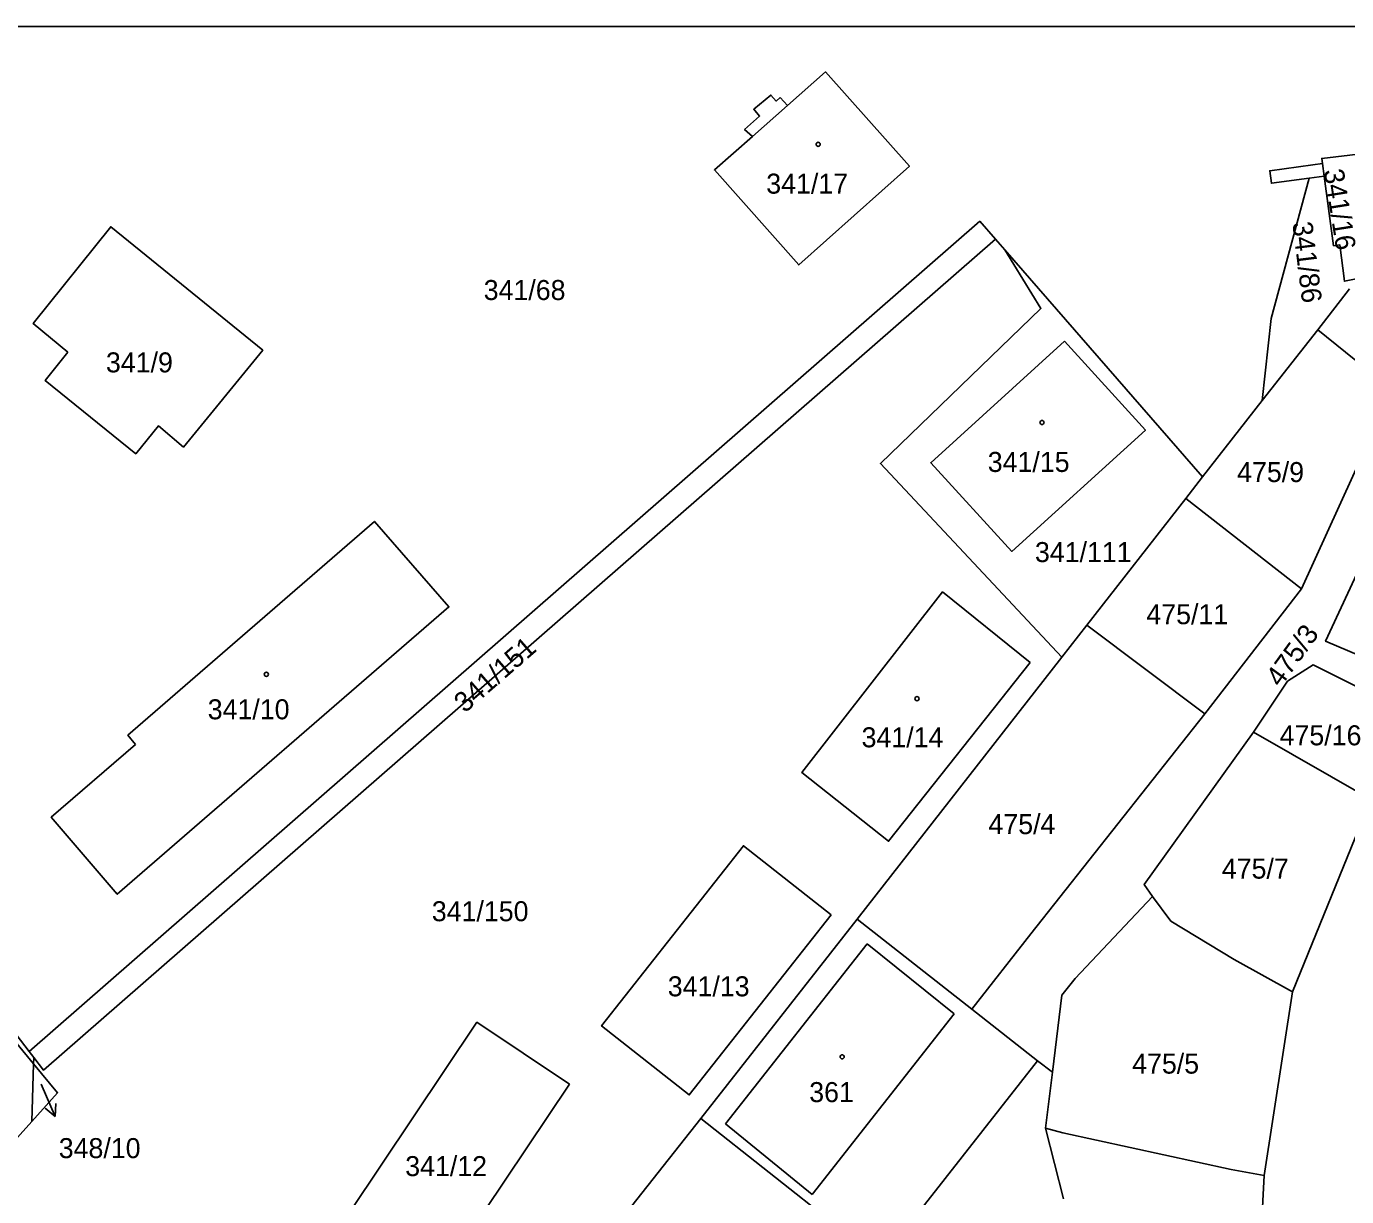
# Model space of a CAD drawing. Extents: x -558358 to -557517, y -1073785 to -1073189.
# Drawn here: x -557909.7 to -557797.5, y -1073289.5 to -1073190.1 of the extents above; entities that cross this region are included whole.
import ezdxf

# ---------------------------------------------------------------- set-up
doc = ezdxf.new("R2010")
doc.units = 0
for name, color, linetype in [('Hranice parcel', 7, 'Continuous'), ('Parcelní čísla', 7, 'Continuous'), ('Pop  PČ popisy', 7, 'Continuous'), ('Rozpiska_pole_1', 7, 'Continuous'), ('Vnitřní kresba', 7, 'Continuous'), ('Značky budov', 7, 'Continuous')]:
    doc.layers.add(name, color=color, linetype=linetype)

msp = doc.modelspace()

# ---------------------------------------------------------------- linework, layer by layer
at = {"layer": 'Hranice parcel'}
for p, q in [((-557909.46, -1073277.19), (-557828.67, -1073206.65)), ((-557828.67, -1073206.65), (-557827.35, -1073208.16)), ((-557827.35, -1073208.16), (-557826.56, -1073209.07)), ((-557826.56, -1073209.07), (-557809.74, -1073228.36)), ((-557797.26, -1073212.4), (-557799.96, -1073215.86)), ((-557799.96, -1073215.86), (-557804.68, -1073221.89)), ((-557809.74, -1073228.36), (-557804.68, -1073221.89)), ((-557809.74, -1073228.36), (-557811.18, -1073230.2)), ((-557811.18, -1073230.2), (-557819.59, -1073240.96)), ((-557811.18, -1073230.2), (-557801.34, -1073237.87)), ((-557801.34, -1073237.87), (-557809.56, -1073248.5)), ((-557819.59, -1073240.96), (-557821.71, -1073243.68)), ((-557809.56, -1073248.5), (-557819.59, -1073240.96)), ((-557821.71, -1073243.68), (-557839.11, -1073265.95)), ((-557795.47, -1073255.77), (-557805.42, -1073250.06)), ((-557909.08, -1073278.25), (-557930.32, -1073252.64)), ((-557802.11, -1073272.13), (-557795.8, -1073256.6)), ((-557839.11, -1073265.95), (-557852.38, -1073282.88)), ((-557829.36, -1073273.59), (-557839.11, -1073265.95)), ((-557804.5, -1073287.75), (-557802.11, -1073272.13)), ((-557823.76, -1073277.98), (-557829.36, -1073273.59)), ((-557909.46, -1073277.19), (-557909.06, -1073277.71)), ((-557909.23, -1073283.14), (-557909.08, -1073278.25)), ((-557909.06, -1073277.71), (-557909.08, -1073278.25)), ((-557837.1, -1073294.96), (-557823.76, -1073277.98)), ((-557823.76, -1073277.98), (-557822.5, -1073278.97)), ((-557822.5, -1073278.97), (-557823.08, -1073283.72)), ((-557912.91, -1073287.22), (-557909.23, -1073283.14)), ((-557852.38, -1073282.88), (-557892.99, -1073334.25)), ((-557852.38, -1073282.88), (-557837.1, -1073294.96)), ((-557821.55, -1073289.72), (-557823.08, -1073283.72)), ((-557805.19, -1073300.2), (-557804.5, -1073287.75))]:
    msp.add_line(p, q, dxfattribs=at)
for points in [[(-557845.64, -1073196.14), (-557845.97, -1073196.44), (-557846.43, -1073195.93), (-557847.88, -1073197.13), (-557847.39, -1073197.71), (-557848.66, -1073198.84), (-557848, -1073199.43), (-557851.22, -1073202.29), (-557844.06, -1073210.35), (-557834.66, -1073201.96), (-557841.8, -1073193.95), (-557845.02, -1073196.82), (-557845.64, -1073196.14)], [(-557794.69, -1073211.15), (-557795, -1073208.24), (-557793.89, -1073208.1), (-557794.86, -1073200.76), (-557799.62, -1073201.3), (-557799.56, -1073201.75), (-557800.39, -1073201.86)], [(-557800.69, -1073202.99), (-557803.9, -1073203.42), (-557804.04, -1073202.35), (-557800.39, -1073201.86)], [(-557800.69, -1073202.99), (-557803.91, -1073214.91), (-557804.68, -1073221.89)], [(-557800.69, -1073202.99), (-557799.42, -1073202.82), (-557798.62, -1073208.73), (-557798.08, -1073208.66), (-557797.7, -1073211.74), (-557794.69, -1073211.15)], [(-557906.17, -1073217.76), (-557908.09, -1073220.19), (-557900.4, -1073226.4), (-557898.47, -1073224.04), (-557896.35, -1073225.84), (-557889.61, -1073217.61), (-557902.52, -1073207.11), (-557909.1, -1073215.34), (-557906.17, -1073217.76)], [(-557827.35, -1073208.16), (-557908.24, -1073278.78), (-557909.06, -1073277.71)], [(-557826.56, -1073209.07), (-557823.48, -1073214.05), (-557837.12, -1073227.22), (-557821.71, -1073243.68)], [(-557799.96, -1073215.86), (-557793.64, -1073220.96), (-557801.34, -1073237.87)], [(-557821.48, -1073216.83), (-557832.85, -1073227.17), (-557825.95, -1073234.71), (-557814.6, -1073224.41), (-557821.48, -1073216.83)], [(-557791.11, -1073245.75), (-557793.29, -1073244.89), (-557799.3, -1073242.34), (-557790.59, -1073223.57), (-557786.97, -1073223.95)], [(-557900.41, -1073251.11), (-557907.58, -1073257.29), (-557901.97, -1073263.84), (-557873.78, -1073239.42), (-557880.11, -1073232.15), (-557901.06, -1073250.32), (-557900.41, -1073251.11)], [(-557824.39, -1073244.13), (-557831.84, -1073238.15), (-557843.81, -1073253.48), (-557836.43, -1073259.33), (-557824.39, -1073244.13)], [(-557805.42, -1073250.06), (-557802.52, -1073245.72), (-557800.36, -1073244.34), (-557792.5, -1073248.24)], [(-557809.56, -1073248.5), (-557824.33, -1073267.21), (-557829.36, -1073273.59)], [(-557814, -1073264.03), (-557814.7, -1073263), (-557805.42, -1073250.06)], [(-557930.24, -1073250.53), (-557916.49, -1073268.06), (-557909.46, -1073277.19)], [(-557841.31, -1073265.58), (-557848.76, -1073259.71), (-557860.82, -1073275.02), (-557853.36, -1073280.89), (-557841.31, -1073265.58)], [(-557822.5, -1073278.97), (-557821.7, -1073272.42), (-557820.57, -1073271), (-557814, -1073264.03)], [(-557802.11, -1073272.13), (-557807.06, -1073269.39), (-557812.44, -1073266.12), (-557814, -1073264.03)], [(-557863.55, -1073279.98), (-557871.4, -1073274.72), (-557882.24, -1073290.87), (-557874.41, -1073296.22), (-557863.55, -1073279.98)], [(-557909.08, -1073278.25), (-557907.04, -1073280.71), (-557909.23, -1073283.14)], [(-557823.08, -1073283.72), (-557821.62, -1073284.11), (-557807.33, -1073287.22), (-557804.5, -1073287.75)]]:
    msp.add_lwpolyline(points, dxfattribs=at)
at = {"layer": 'Pop  PČ popisy'}
for p, q in [((-557908.42, -1073279.97), (-557907.25, -1073282.73)), ((-557907.25, -1073282.73), (-557907.18, -1073281.61)), ((-557907.25, -1073282.73), (-557908.1, -1073282.01))]:
    msp.add_line(p, q, dxfattribs=at)
at = {"layer": 'Rozpiska_pole_1'}
msp.add_line((-558357.53, -1073190.09), (-557516.53, -1073190.09), dxfattribs=at)
at = {"layer": 'Vnitřní kresba'}
for p, q in [((-557848, -1073199.43), (-557845.02, -1073196.82)), ((-557799.56, -1073201.75), (-557799.42, -1073202.82)), ((-557850.28, -1073283.35), (-557838.25, -1073268.06)), ((-557838.25, -1073268.06), (-557830.86, -1073274.01)), ((-557842.92, -1073289.34), (-557830.86, -1073274.01)), ((-557850.28, -1073283.35), (-557842.92, -1073289.34))]:
    msp.add_line(p, q, dxfattribs=at)
at = {"layer": 'Značky budov'}
for centre in [(-557842.41, -1073200.11), (-557823.39, -1073223.75), (-557889.3, -1073245.15), (-557834.01, -1073247.22), (-557840.37, -1073277.65)]:
    msp.add_circle(centre, 0.175, dxfattribs=at)

# ---------------------------------------------------------------- texts
at = {"layer": 'Parcelní čísla'}
for s, p in [('341/17', (-557846.82, -1073204.3)), ('341/68', (-557870.83, -1073213.34)), ('341/9', (-557902.93, -1073219.49)), ('341/15', (-557828, -1073227.95)), ('475/9', (-557806.81, -1073228.81)), ('341/111', (-557823.99, -1073235.61)), ('475/11', (-557814.52, -1073240.89)), ('341/10', (-557894.28, -1073248.97)), ('341/14', (-557838.72, -1073251.35)), ('475/16', (-557803.2, -1073251.18)), ('475/4', (-557827.94, -1073258.73)), ('475/7', (-557808.11, -1073262.51)), ('341/150', (-557875.24, -1073266.13)), ('341/13', (-557855.19, -1073272.51)), ('475/5', (-557815.73, -1073279.08)), ('361', (-557843.17, -1073281.5)), ('348/10', (-557906.94, -1073286.26)), ('341/12', (-557877.5, -1073287.79))]:
    msp.add_text(s, height=1.7, dxfattribs=at).set_placement(p)
for s, rotation, p in [('341/16', 279, (-557799.46, -1073202.33)), ('341/86', 277, (-557802.12, -1073206.77)), ('475/3', 54, (-557803.13, -1073246.32)), ('341/151', 41, (-557872.43, -1073248.49))]:
    msp.add_text(s, height=1.7, rotation=rotation, dxfattribs=at).set_placement(p)

doc.saveas('drawing.dxf')
